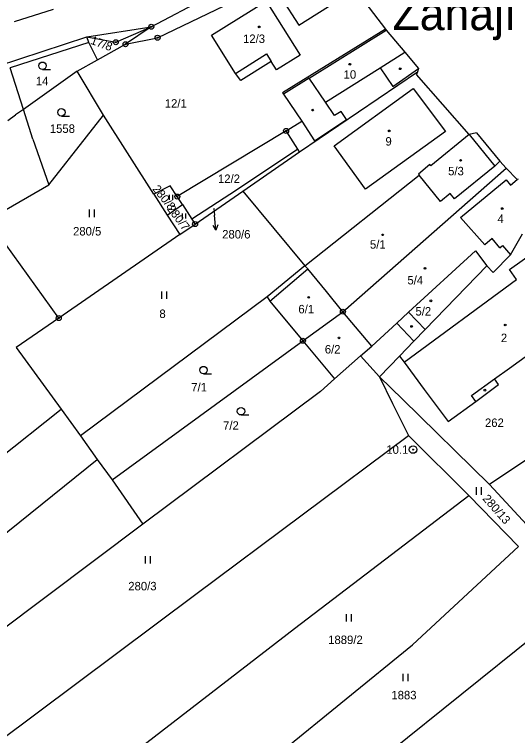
# Model space of a CAD drawing. Extents: x -762263 to -760336, y -1154405 to -1152076.
# Drawn here: x -761696.3 to -761595.2, y -1152630.1 to -1152485.2 of the extents above; entities that cross this region are included whole.
import ezdxf

# ---------------------------------------------------------------- set-up
doc = ezdxf.new("R2010")
doc.units = 0
for name, color, linetype in [('Vrstva 1', 7, 'Continuous'), ('Vrstva 15', 7, 'Continuous'), ('Vrstva 16', 7, 'Continuous'), ('Vrstva 17', 7, 'Continuous'), ('Vrstva 18', 7, 'Continuous'), ('Vrstva 19', 7, 'Continuous'), ('Vrstva 24', 7, 'Continuous'), ('Vrstva 25', 7, 'Continuous'), ('Vrstva 4', 7, 'Continuous'), ('Vrstva 6', 7, 'Continuous')]:
    doc.layers.add(name, color=color, linetype=linetype)

msp = doc.modelspace()

# ---------------------------------------------------------------- linework, layer by layer
at = {"layer": 'Vrstva 1'}
for p, q in [((-761668.79, -1152487.64), (-761637.76, -1152471.22)), ((-761667.53, -1152489.85), (-761635.67, -1152474.5)), ((-761629.01, -1152478.46), (-761621.74, -1152488.11)), ((-761642.66, -1152481.75), (-761639.13, -1152487.35)), ((-761656.67, -1152489.36), (-761645.72, -1152482.48)), ((-761645.72, -1152482.48), (-761638.89, -1152493.34)), ((-761639.13, -1152487.35), (-761631.37, -1152482.45)), ((-761688.52, -1152484.19), (-761696.37, -1152486.69)), ((-761675.94, -1152490.75), (-761668.79, -1152487.64)), ((-761668.79, -1152487.64), (-761673.97, -1152491.16)), ((-761651.85, -1152497.01), (-761656.67, -1152489.36)), ((-761621.74, -1152488.11), (-761642.44, -1152500.96)), ((-761621.74, -1152488.11), (-761621.55, -1152488.34)), ((-761621.55, -1152488.34), (-761617.85, -1152492.77)), ((-761737.23, -1152507.93), (-761681.78, -1152489.69)), ((-761681.36, -1152490.81), (-761697.2, -1152495.91)), ((-761681.78, -1152489.69), (-761675.94, -1152490.75)), ((-761679.58, -1152494.28), (-761681.36, -1152490.81)), ((-761673.97, -1152491.16), (-761667.53, -1152489.85)), ((-761679.58, -1152494.28), (-761673.97, -1152491.16)), ((-761638.89, -1152493.34), (-761643.62, -1152496.3)), ((-761617.85, -1152492.77), (-761615.1, -1152496.05)), ((-761683.67, -1152496.56), (-761679.58, -1152494.28)), ((-761644.68, -1152494.61), (-761650.79, -1152498.45)), ((-761643.62, -1152496.3), (-761644.68, -1152494.61)), ((-761694.51, -1152504.25), (-761697.2, -1152495.91)), ((-761678.43, -1152505.43), (-761683.67, -1152496.56)), ((-761639.01, -1152512.82), (-761615.31, -1152496.69)), ((-761615.31, -1152496.69), (-761615.51, -1152497.25)), ((-761615.1, -1152496.05), (-761615.31, -1152496.69)), ((-761650.79, -1152498.45), (-761651.85, -1152497.01)), ((-761604.88, -1152509.27), (-761615.51, -1152497.25)), ((-761642.44, -1152500.96), (-761642.25, -1152501.19)), ((-761642.25, -1152501.19), (-761638.55, -1152506.65)), ((-761692.59, -1152510.23), (-761694.51, -1152504.25)), ((-761681.84, -1152509.78), (-761678.43, -1152505.43)), ((-761668.29, -1152521.3), (-761678.43, -1152505.43)), ((-761641.7, -1152508.59), (-761638.55, -1152506.65)), ((-761689.38, -1152519.4), (-761681.84, -1152509.78)), ((-761641.7, -1152508.59), (-761663.57, -1152521.78)), ((-761639.35, -1152512.28), (-761641.7, -1152508.59)), ((-761604.88, -1152509.27), (-761612.61, -1152515.6)), ((-761603.43, -1152508.99), (-761604.88, -1152509.27)), ((-761603.43, -1152508.99), (-761598.72, -1152514.65)), ((-761692.59, -1152510.23), (-761689.38, -1152519.4)), ((-761639.35, -1152512.28), (-761651.65, -1152520.48)), ((-761639.01, -1152512.82), (-761639.35, -1152512.28)), ((-761650.37, -1152520.66), (-761639.01, -1152512.82)), ((-761612.8, -1152515.36), (-761615.11, -1152517.25)), ((-761612.61, -1152515.6), (-761612.8, -1152515.36)), ((-761598.72, -1152514.65), (-761599.71, -1152515.66)), ((-761597.46, -1152516.07), (-761598.72, -1152514.65)), ((-761630.29, -1152544.91), (-761597.46, -1152516.07)), ((-761599.71, -1152515.66), (-761607.84, -1152522.23)), ((-761595.28, -1152518.37), (-761597.46, -1152516.07)), ((-761637.9, -1152535.71), (-761614.94, -1152517.45)), ((-761615.11, -1152517.25), (-761614.94, -1152517.45)), ((-761610.69, -1152522.78), (-761614.94, -1152517.45)), ((-761606.64, -1152525.97), (-761597.46, -1152518.42)), ((-761597.46, -1152518.42), (-761596.57, -1152519.5)), ((-761596.57, -1152519.5), (-761595.28, -1152518.37)), ((-761595.05, -1152518.25), (-761595.28, -1152518.37)), ((-761701.65, -1152526.45), (-761689.38, -1152519.4)), ((-761664.98, -1152519.59), (-761668.29, -1152521.3)), ((-761663.57, -1152521.78), (-761664.98, -1152519.59)), ((-761668.29, -1152521.3), (-761665.6, -1152525.49)), ((-761651.65, -1152520.48), (-761660.63, -1152526.33)), ((-761660, -1152527.3), (-761650.37, -1152520.66)), ((-761650.37, -1152520.66), (-761637.9, -1152535.71)), ((-761608.7, -1152521.17), (-761610.69, -1152522.78)), ((-761607.84, -1152522.23), (-761608.7, -1152521.17)), ((-761662.54, -1152523.37), (-761663.57, -1152521.78)), ((-761665.6, -1152525.49), (-761662.54, -1152523.37)), ((-761662.54, -1152523.37), (-761660.63, -1152526.33)), ((-761665.6, -1152525.49), (-761663.09, -1152529.43)), ((-761687.39, -1152546.2), (-761701.65, -1152526.45)), ((-761660.63, -1152526.33), (-761660, -1152527.3)), ((-761601.78, -1152531.5), (-761606.64, -1152525.97)), ((-761663.09, -1152529.43), (-761660, -1152527.3)), ((-761663.09, -1152529.43), (-761687.39, -1152546.2)), ((-761596.59, -1152533.46), (-761594.15, -1152529.24)), ((-761600.3, -1152530.22), (-761601.78, -1152531.5)), ((-761598.7, -1152532.07), (-761600.3, -1152530.22)), ((-761617.06, -1152545.04), (-761603.62, -1152532.69)), ((-761603.62, -1152532.69), (-761601.34, -1152535.71)), ((-761598.7, -1152532.07), (-761598.17, -1152531.61)), ((-761598.17, -1152531.61), (-761596.59, -1152533.46)), ((-761596.59, -1152533.46), (-761600.1, -1152537.02)), ((-761637.9, -1152535.71), (-761645.53, -1152541.96)), ((-761637.35, -1152536.33), (-761637.9, -1152535.71)), ((-761601.34, -1152535.71), (-761613.76, -1152548.51)), ((-761600.1, -1152537.02), (-761601.34, -1152535.71)), ((-761633.58, -1152540.88), (-761637.35, -1152536.33)), ((-761630.29, -1152544.91), (-761633.58, -1152540.88)), ((-761645.53, -1152541.96), (-761683.03, -1152569.86)), ((-761645.53, -1152541.96), (-761645, -1152542.77)), ((-761645, -1152542.77), (-761638.32, -1152550.76)), ((-761638.32, -1152550.76), (-761630.29, -1152544.91)), ((-761624.44, -1152551.83), (-761630.29, -1152544.91)), ((-761619.43, -1152547.22), (-761617.06, -1152545.04)), ((-761687.39, -1152546.2), (-761695.97, -1152552.12)), ((-761624.44, -1152551.83), (-761619.43, -1152547.22)), ((-761613.76, -1152548.51), (-761616.01, -1152550.83)), ((-761596.82, -1152556.24), (-761588, -1152549.86)), ((-761676.69, -1152578.69), (-761638.32, -1152550.76)), ((-761638.32, -1152550.76), (-761631.95, -1152558.43)), ((-761618.92, -1152553.83), (-761616.01, -1152550.83)), ((-761695.97, -1152552.12), (-761686.92, -1152564.53)), ((-761626.71, -1152553.82), (-761624.44, -1152551.83)), ((-761631.95, -1152558.43), (-761626.71, -1152553.82)), ((-761626.71, -1152553.82), (-761622.95, -1152557.98)), ((-761622.95, -1152557.98), (-761618.92, -1152553.83)), ((-761618.92, -1152553.83), (-761617.99, -1152555.08)), ((-761617.99, -1152555.08), (-761613.92, -1152560.57)), ((-761599.82, -1152558.41), (-761596.82, -1152556.24)), ((-761634.76, -1152560.93), (-761631.95, -1152558.43)), ((-761622.95, -1152557.98), (-761620.28, -1152563.39)), ((-761622.95, -1152557.98), (-761618.32, -1152562.52)), ((-761598.98, -1152559.58), (-761599.82, -1152558.41)), ((-761603.56, -1152562.96), (-761598.98, -1152559.58)), ((-761634.76, -1152560.93), (-761670.53, -1152587.64)), ((-761613.92, -1152560.57), (-761609.15, -1152567)), ((-761620.28, -1152563.39), (-761617.1, -1152569.83)), ((-761618.32, -1152562.52), (-761600.84, -1152579.67)), ((-761609.15, -1152567), (-761603.56, -1152562.96)), ((-761686.92, -1152564.53), (-761683.03, -1152569.86)), ((-761683.03, -1152569.86), (-761679.66, -1152574.65)), ((-761659.83, -1152601.72), (-761617.1, -1152569.83)), ((-761587.4, -1152570.64), (-761600.84, -1152579.67)), ((-761679.66, -1152574.65), (-761676.69, -1152578.69)), ((-761676.69, -1152578.69), (-761670.53, -1152587.64)), ((-761600.84, -1152579.67), (-761579.44, -1152602.7)), ((-761670.53, -1152587.64), (-761717.16, -1152622.54)), ((-761706.64, -1152636.65), (-761659.83, -1152601.72))]:
    msp.add_line(p, q, dxfattribs=at)
at = {"layer": 'Vrstva 16'}
for p in [(-761656.24, -1152524.16), (-761655.79, -1152528.504)]:
    msp.add_line(p, (-761656.1, -1152525.52), dxfattribs=at)
msp.add_lwpolyline([(-761655.396, -1152527.458), (-761655.79, -1152528.504), (-761656.391, -1152527.561)], dxfattribs=at)
at = {"layer": 'Vrstva 24'}
for centre, radius in [((-761668.79, -1152487.64), 0.5), ((-761668.79, -1152487.64), 0.1), ((-761667.53, -1152489.85), 0.5), ((-761675.94, -1152490.75), 0.5), ((-761675.94, -1152490.75), 0.1), ((-761673.97, -1152491.16), 0.5), ((-761667.53, -1152489.85), 0.1), ((-761673.97, -1152491.16), 0.1), ((-761641.7, -1152508.59), 0.5), ((-761641.7, -1152508.59), 0.1), ((-761663.57, -1152521.78), 0.5), ((-761663.57, -1152521.78), 0.1), ((-761660, -1152527.3), 0.5), ((-761660, -1152527.3), 0.1), ((-761630.29, -1152544.91), 0.5), ((-761687.39, -1152546.2), 0.5), ((-761630.29, -1152544.91), 0.1), ((-761687.39, -1152546.2), 0.1), ((-761638.32, -1152550.76), 0.5), ((-761638.32, -1152550.76), 0.1), ((-761616.18, -1152572.63), 0.75), ((-761616.18, -1152572.63), 0.1)]:
    msp.add_circle(centre, radius, dxfattribs=at)
at = {"layer": 'Vrstva 25'}
for p, q in [((-761690.66, -1152496.24), (-761689.06, -1152496.24)), ((-761686.86, -1152505.6), (-761685.26, -1152505.6)), ((-761665.165, -1152522.43), (-761665.165, -1152521.425)), ((-761664.495, -1152522.43), (-761664.495, -1152521.425)), ((-761681.21, -1152525.9), (-761681.21, -1152524.4)), ((-761680.21, -1152525.9), (-761680.21, -1152524.4)), ((-761662.545, -1152526.19), (-761662.545, -1152525.185)), ((-761661.875, -1152526.19), (-761661.875, -1152525.185)), ((-761666.69, -1152542.36), (-761666.69, -1152540.86)), ((-761665.69, -1152542.36), (-761665.69, -1152540.86)), ((-761658.3, -1152557.4), (-761656.7, -1152557.4)), ((-761650.76, -1152565.67), (-761649.16, -1152565.67)), ((-761603.42, -1152581.71), (-761603.42, -1152580.21)), ((-761602.42, -1152581.71), (-761602.42, -1152580.21)), ((-761669.94, -1152595.52), (-761669.94, -1152594.02)), ((-761668.94, -1152595.52), (-761668.94, -1152594.02)), ((-761629.57, -1152607.21), (-761629.57, -1152605.71)), ((-761628.57, -1152607.21), (-761628.57, -1152605.71)), ((-761618.19, -1152619.18), (-761618.19, -1152617.68)), ((-761617.19, -1152619.18), (-761617.19, -1152617.68))]:
    msp.add_line(p, q, dxfattribs=at)
for points in [[(-761622.2, -1152529.32), (-761622.11, -1152529.47), (-761622.2, -1152529.62), (-761622.38, -1152529.62), (-761622.47, -1152529.47), (-761622.38, -1152529.32)], [(-761613.68, -1152536.05), (-761613.59, -1152536.2), (-761613.68, -1152536.35), (-761613.86, -1152536.35), (-761613.95, -1152536.2), (-761613.86, -1152536.05)]]:
    msp.add_lwpolyline(points, close=True, dxfattribs=at)
for centre, radius in [((-761647.1, -1152487.68), 0.175), ((-761690.66, -1152495.49), 0.75), ((-761628.88, -1152495.18), 0.175), ((-761618.76, -1152496.09), 0.175), ((-761686.86, -1152504.85), 0.75), ((-761636.35, -1152504.39), 0.175), ((-761620.96, -1152508.58), 0.175), ((-761606.61, -1152514.5), 0.175), ((-761598.25, -1152524.19), 0.175), ((-761637.16, -1152542.03), 0.175), ((-761612.58, -1152542.73), 0.175), ((-761597.65, -1152547.58), 0.175), ((-761616.48, -1152547.88), 0.175), ((-761631.07, -1152550.18), 0.175), ((-761658.3, -1152556.65), 0.75), ((-761601.73, -1152560.68), 0.175), ((-761650.76, -1152564.92), 0.75)]:
    msp.add_circle(centre, radius, dxfattribs=at)
at = {"layer": 'Vrstva 4'}
for p, q in [((-761681.78, -1152489.69), (-761668.79, -1152487.64)), ((-761637.04, -1152497.95), (-761621.55, -1152488.34)), ((-761651.85, -1152497.01), (-761645.63, -1152493.1)), ((-761645.63, -1152493.1), (-761644.68, -1152494.61)), ((-761622.79, -1152495.88), (-761617.85, -1152492.77)), ((-761633.79, -1152502.81), (-761622.79, -1152495.88)), ((-761622.79, -1152495.88), (-761620.23, -1152499.66)), ((-761620.23, -1152499.66), (-761615.1, -1152496.05)), ((-761637.04, -1152497.95), (-761642.25, -1152501.19)), ((-761633.79, -1152502.81), (-761637.04, -1152497.95)), ((-761632.06, -1152511.57), (-761616.18, -1152500.05)), ((-761616.18, -1152500.05), (-761609.68, -1152508.68)), ((-761631.99, -1152505.5), (-761633.79, -1152502.81)), ((-761630.64, -1152504.69), (-761631.99, -1152505.5)), ((-761629.58, -1152506.26), (-761630.64, -1152504.69)), ((-761638.55, -1152506.65), (-761635.99, -1152510.6)), ((-761635.99, -1152510.6), (-761629.58, -1152506.26)), ((-761609.68, -1152508.68), (-761625.71, -1152520.32)), ((-761604.88, -1152509.27), (-761599.71, -1152515.66)), ((-761625.71, -1152520.32), (-761632.06, -1152511.57)), ((-761596.81, -1152536.41), (-761591.45, -1152532.6)), ((-761645, -1152542.77), (-761637.35, -1152536.33)), ((-761595.38, -1152538.43), (-761596.81, -1152536.41)), ((-761617.99, -1152555.08), (-761595.38, -1152538.43)), ((-761613.76, -1152548.51), (-761617.06, -1152545.04)), ((-761619.43, -1152547.22), (-761616.01, -1152550.83)), ((-761604.41, -1152561.76), (-761599.82, -1152558.41)), ((-761603.56, -1152562.96), (-761604.41, -1152561.76))]:
    msp.add_line(p, q, dxfattribs=at)
at = {"layer": 'Vrstva 6'}
for p, q in [((-761681.36, -1152490.81), (-761681.78, -1152489.69)), ((-761683.67, -1152496.56), (-761694.51, -1152504.25)), ((-761697.65, -1152506.48), (-761696.09, -1152505.37)), ((-761694.51, -1152504.25), (-761696.09, -1152505.37)), ((-761741.33, -1152607.69), (-761686.92, -1152564.53)), ((-761604.99, -1152581.83), (-761617.1, -1152569.83)), ((-761726.39, -1152612.2), (-761679.66, -1152574.65)), ((-761639.98, -1152608.57), (-761604.99, -1152581.83)), ((-761604.99, -1152581.83), (-761595.01, -1152592.12)), ((-761616.31, -1152611.88), (-761595.01, -1152592.12)), ((-761583.91, -1152603.67), (-761641.55, -1152650.06)), ((-761672.04, -1152633.28), (-761639.98, -1152608.57)), ((-761655.88, -1152644.04), (-761616.31, -1152611.88))]:
    msp.add_line(p, q, dxfattribs=at)

# ---------------------------------------------------------------- texts
at = {"layer": 'Vrstva 15'}
msp.add_text('Zahájí', height=6.7, dxfattribs=at).set_placement((-761620.305, -1152488.33))
at = {"layer": 'Vrstva 16'}
msp.add_text('280/6', height=1.7, dxfattribs=at).set_placement((-761654.553, -1152530.2))
at = {"layer": 'Vrstva 17'}
msp.add_text('10.1', height=1.7, dxfattribs=at).set_placement((-761621.545, -1152573.48))
at = {"layer": 'Vrstva 18'}
for s, rotation, p in [('17/8', 339.87856, (-761681.151, -1152491.043)), ('280/8', 308.76696, (-761668.662, -1152520.288)), ('280/7', 307.27727, (-761665.732, -1152524.269)), ('280/13', 311.34527, (-761602.315, -1152582.556))]:
    msp.add_text(s, height=1.7, rotation=rotation, dxfattribs=at).set_placement(p)
for s, height, p in [('14', 1.7, (-761692.007, -1152499.41)), ('12/1', 1.7, (-761666.091, -1152503.91)), ('1558', 1.7, (-761689.199, -1152508.98)), ('12/2', 1.7, (-761655.393, -1152519.04)), ('280/6', 0.1, (-761656.449, -1152524.16)), ('280/5', 1.7, (-761684.527, -1152529.6)), ('8', 1.7, (-761667.166, -1152546.18)), ('7/1', 1.7, (-761660.766, -1152560.94)), ('7/2', 1.7, (-761654.368, -1152568.64)), ('262', 1.7, (-761601.721, -1152568.08)), ('280/3', 1.7, (-761673.427, -1152600.92)), ('1889/2', 1.7, (-761633.242, -1152611.71)), ('1883', 1.7, (-761620.536, -1152622.82))]:
    msp.add_text(s, height=height, dxfattribs=at).set_placement(p)
at = {"layer": 'Vrstva 19'}
for s, p in [('12/3', (-761650.357, -1152490.91)), ('10', (-761630.134, -1152498.09)), ('9', (-761621.726, -1152511.53)), ('5/3', (-761609.129, -1152517.51)), ('4', (-761599.196, -1152527.08)), ('5/1', (-761624.843, -1152532.25)), ('5/4', (-761617.311, -1152539.43)), ('6/1', (-761639.227, -1152545.25)), ('5/2', (-761615.695, -1152545.69)), ('2', (-761598.519, -1152551.03)), ('6/2', (-761633.918, -1152553.32))]:
    msp.add_text(s, height=1.7, dxfattribs=at).set_placement(p)

doc.saveas('drawing.dxf')
